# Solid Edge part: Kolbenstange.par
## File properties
Username: bmolnar
Dokumentum tartalom típus: 0
Author: bmolnar
Last saved by: bmolnar
Revision: 80
Sűrűség: 0,000 kg/m^3
Pontosság: 0,990
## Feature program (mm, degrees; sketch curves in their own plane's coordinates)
base feature "unnamed BaseFeature 1"
sketch for "unnamed Protrusion 1" plane through (30, 0, 0) normal (1, 0, 0) x-axis (0, -1, 0)
  circle centre (0, 0) radius 25
extrude "unnamed Protrusion 1" add finite 8.5 along +normal
sketch for "Kihúzás_2" plane through (30, 0, 0) normal (1, 0, 0) x-axis (0, -1, 0)
  circle centre (0, 0) radius 25
extrude "Kihúzás_2" add finite 7.5 along -normal
sketch for "Furat_2" plane through (-15, 0, 0) normal (-1, 0, 0) x-axis (0, 0, -1)
  hole centre (0, 0) bore radius 4.188
hole "Furat_2" nominal diameter 10 finite  ThreadDepth = 17 mm
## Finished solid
Body 1: solid body, 14 faces, 20 edges, 8 vertices.
  Faces by surface: plane 8, cylinder 4, cone 1, torus 1
  Edges by curve: circle 10, line 6, ellipse 2, intersection 2
Bounding box of the edges (mm; curved faces can reach further): 53.500 x 50.000 x 50.000, from (-15, -25, -25) to (38.5, 25, 25).
Cylindrical faces by radius (mm): R4.188 x2, R8 x1, R25 x1
Conical faces (half-angle, radius in mm at the cone's reference point): 45 deg R4.538 x1
Toroidal faces (ring radius, tube radius in mm): R6.3 r1.7 x1
Planar faces by outward normal: +x 1, +z 1, -x 3, -z 1, oblique 2
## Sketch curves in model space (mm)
circle centre (30, 0, 0) radius 25
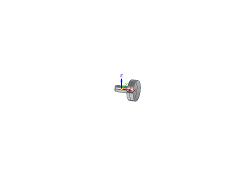
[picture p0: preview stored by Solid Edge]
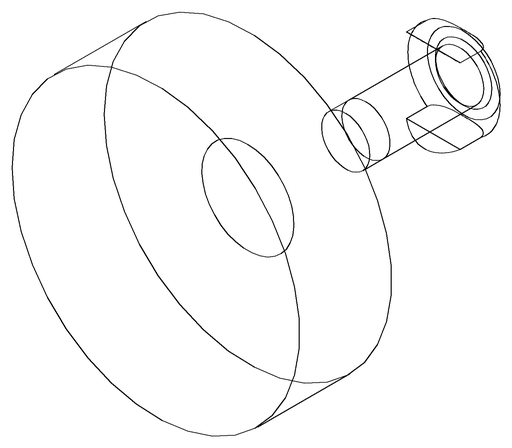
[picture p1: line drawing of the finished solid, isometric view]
